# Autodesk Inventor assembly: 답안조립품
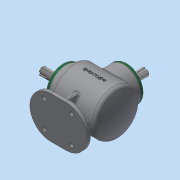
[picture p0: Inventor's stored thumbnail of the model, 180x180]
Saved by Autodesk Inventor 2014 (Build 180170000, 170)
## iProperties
Created: 2023-01
Part Number: 답안조립품
Document SubType Name: Assembly
Designer: dg
Author: dg
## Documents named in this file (14)
- C:\Users\dg\Desktop\730106V1018\답안조립품.iam
- C:\Users\dg\Desktop\730106V1018\본체.ipt
- C:\Users\dg\Desktop\730106V1018\메인 베벨기어.ipt
- C:\Users\dg\Desktop\730106V1018\메인 축.ipt
- 메인 축.ipt
- C:\Users\dg\Desktop\730106V1018\베어링 6203.ipt
- C:\Users\dg\Desktop\730106V1018\오일실 17 32 8.ipt
- C:\Users\dg\Desktop\730106V1018\커버.ipt
- C:\Users\dg\Desktop\730106V1018\서브 베벨기어.ipt
- C:\Users\dg\Desktop\730106V1018\서브 축.ipt
- 서브 축.ipt
- C:\Users\dg\Desktop\730106V1018\키 4x4.ipt
- C:\Users\dg\Desktop\730106V1018\키 5x5.ipt
- C:\Users\dg\Desktop\730106V1018\M4.ipt
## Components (8 placed, 1 different names)
1. M4:1
2. M4:2
3. M4:3
4. M4:4
5. M4:5
6. M4:6
7. M4:7
8. M4:8
